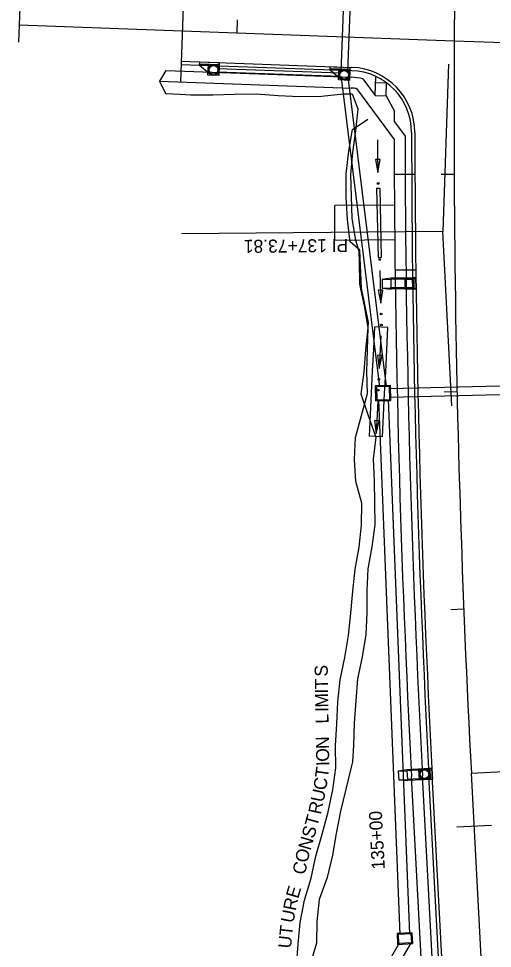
# Model space of a CAD drawing. Extents: x 979959 to 994833, y 1835619 to 1845316.
# Drawn here: x 992272.6 to 992490.3, y 1842198 to 1842625.6 of the extents above; entities that cross this region are included whole.
import ezdxf

# ---------------------------------------------------------------- set-up
doc = ezdxf.new("R2010")
doc.units = 0
for name, color, linetype in [('Future 5 Lane Construction Limits', 7, 'Continuous'), ('R_Drainage', 7, 'Continuous'), ('R_Horz Alg', 7, 'Continuous'), ('R_Horz Alg Annot', 7, 'Continuous'), ('R_Horz Alg Stationing', 7, 'Continuous'), ('R_Proposed Const Limits', 7, 'Continuous'), ('R_Proposed Road', 7, 'Continuous'), ('R_Special Ditch', 7, 'Continuous')]:
    doc.layers.add(name, color=color, linetype=linetype)

msp = doc.modelspace()

# ---------------------------------------------------------------- linework, layer by layer
at = {"layer": 'Future 5 Lane Construction Limits'}
for points in [[(992424.99, 1842522.95), (992423.66, 1842533.28), (992423.12, 1842543.66), (992423.06, 1842554.19), (992424.38, 1842564.68), (992425.98, 1842574.54), (992433.05, 1842579.38)], [(992429.11, 1842382.52), (992430.18, 1842392.64), (992430.37, 1842402.73), (992427.61, 1842412.74), (992427, 1842422.81), (992427.41, 1842432.9), (992430.07, 1842443.05), (992432.92, 1842453.19), (992432.65, 1842463.26), (992432.83, 1842473.34), (992433.22, 1842483.42), (992433.3, 1842485.84), (992430.21, 1842501.66), (992429.45, 1842519.17), (992424.99, 1842522.95)], [(992418.2, 1842291.13), (992418.74, 1842301.27), (992419.28, 1842311.41), (992420.36, 1842321.58), (992422.48, 1842331.78), (992422.96, 1842334.52), (992424.1, 1842341.95), (992425.17, 1842352.1), (992426.21, 1842362.23), (992427.21, 1842372.36), (992429.11, 1842382.52)], [(992400.25, 1842189.87), (992400.98, 1842199.92), (992402.01, 1842209.99), (992404.02, 1842220.11), (992406.97, 1842230.28), (992409.13, 1842240.41), (992412.07, 1842250.58), (992414.81, 1842260.74), (992416.98, 1842270.87), (992418.37, 1842281.01), (992418.2, 1842291.13)]]:
    msp.add_lwpolyline(points, dxfattribs=at)
at = {"layer": 'R_Drainage'}
for p, q in [((992421.89, 1842633.32), (992420.71, 1842601.17)), ((992424.89, 1842633.21), (992423.7, 1842601.06)), ((992355.77, 1842604.23), (992360.56, 1842600.1)), ((992364.79, 1842604.4), (992355.79, 1842604.73)), ((992364.6, 1842599.4), (992359.61, 1842599.58)), ((992364.02, 1842601.17), (992420.28, 1842599.11)), ((992364.08, 1842602.67), (992420.33, 1842600.61)), ((992415.73, 1842602.03), (992420.52, 1842597.9)), ((992424.75, 1842602.2), (992415.75, 1842602.53)), ((992424.56, 1842597.2), (992419.57, 1842597.39)), ((992420.83, 1842598.3), (992438.49, 1842456.32)), ((992423.81, 1842598.67), (992441.5, 1842456.38)), ((992437.08, 1842547.67), (992438.58, 1842547.7)), ((992437.08, 1842547.67), (992437.73, 1842515.68)), ((992438.58, 1842547.7), (992439.23, 1842515.71)), ((992437.73, 1842515.68), (992439.23, 1842515.71)), ((992443.65, 1842506.24), (992439.65, 1842505.7)), ((992439.65, 1842505.7), (992443.65, 1842505.74)), ((992439.65, 1842505.7), (992439.69, 1842501.7)), ((992454.15, 1842506.34), (992443.65, 1842506.24)), ((992453.65, 1842505.84), (992443.65, 1842505.74)), ((992443.65, 1842505.74), (992443.69, 1842501.74)), ((992453.65, 1842505.84), (992453.69, 1842501.84)), ((992454.15, 1842506.34), (992454.2, 1842501.34)), ((992439.69, 1842501.7), (992443.69, 1842501.74)), ((992439.69, 1842501.7), (992443.7, 1842501.24)), ((992453.69, 1842501.84), (992443.69, 1842501.74)), ((992454.2, 1842501.34), (992443.7, 1842501.24)), ((992453.7, 1842501.34), (992455.2, 1842501.35)), ((992442.3, 1842483.57), (992436.32, 1842483.89)), ((992505.5, 1842456.8), (992443.02, 1842455.42)), ((992437.88, 1842450.3), (992447.74, 1842204.4)), ((992442.38, 1842450.4), (992452.24, 1842204.64)), ((992505.59, 1842452.8), (992443.11, 1842451.42)), ((992439.79, 1842433.22), (992433.8, 1842433.51)), ((992451, 1842280.19), (992447.03, 1842279.48)), ((992447.03, 1842279.48), (992451.03, 1842279.69)), ((992447.03, 1842279.48), (992447.24, 1842275.48)), ((992461.48, 1842280.75), (992451, 1842280.19)), ((992461.01, 1842280.22), (992451.03, 1842279.69)), ((992451.03, 1842279.69), (992451.24, 1842275.7)), ((992456.76, 1842275.49), (992456.49, 1842280.48)), ((992461.01, 1842280.22), (992461.22, 1842276.23)), ((992461.48, 1842280.75), (992461.75, 1842275.75)), ((992447.24, 1842275.48), (992451.24, 1842275.7)), ((992447.24, 1842275.48), (992451.27, 1842275.2)), ((992461.22, 1842276.23), (992451.24, 1842275.7)), ((992461.75, 1842275.75), (992451.27, 1842275.2)), ((992461.25, 1842275.73), (992462.75, 1842275.81)), ((992447.51, 1842200.38), (992384.95, 1842093.69)), ((992452.89, 1842200.67), (992388.83, 1842091.42))]:
    msp.add_line(p, q, dxfattribs=at)
for points in [[(992364.77, 1842603.9), (992355.77, 1842604.23), (992355.83, 1842605.73), (992364.82, 1842605.4)], [(992364.6, 1842599.4), (992359.61, 1842599.58), (992359.79, 1842604.58), (992364.79, 1842604.4)], [(992424.73, 1842601.7), (992415.73, 1842602.03), (992415.79, 1842603.53), (992424.78, 1842603.2)], [(992424.56, 1842597.2), (992419.57, 1842597.39), (992419.75, 1842602.38), (992424.75, 1842602.2)], [(992450.19, 1842501.31), (992450.15, 1842506.31), (992454.15, 1842506.34), (992454.19, 1842501.34)], [(992450.15, 1842506.31), (992450.19, 1842501.31), (992454.19, 1842501.34), (992454.15, 1842506.34)], [(992450.69, 1842501.81), (992450.65, 1842505.81), (992453.65, 1842505.84), (992453.69, 1842501.84)], [(992450.65, 1842505.81), (992450.69, 1842501.81), (992453.69, 1842501.84), (992453.65, 1842505.84)], [(992453.69, 1842501.34), (992453.65, 1842506.34), (992455.15, 1842506.35), (992455.19, 1842501.35)], [(992436.64, 1842449.77), (992443.64, 1842449.93), (992443.48, 1842456.93), (992436.49, 1842456.77)], [(992437.13, 1842450.29), (992443.13, 1842450.42), (992443, 1842456.42), (992437, 1842456.28)], [(992456.76, 1842275.49), (992456.49, 1842280.48), (992461.48, 1842280.74), (992461.75, 1842275.75)], [(992461.25, 1842275.72), (992460.99, 1842280.72), (992462.48, 1842280.8), (992462.75, 1842275.8)], [(992446.73, 1842199.84), (992453.72, 1842200.21), (992453.46, 1842205.2), (992446.47, 1842204.83)], [(992447.2, 1842200.36), (992453.2, 1842200.68), (992452.98, 1842204.68), (992446.99, 1842204.36)]]:
    msp.add_lwpolyline(points, close=True, dxfattribs=at)
for points in [[(992455.2, 1842501.35), (992455.15, 1842506.35), (992453.65, 1842506.34), (992453.7, 1842501.34)], [(992433.8, 1842433.51), (992434.75, 1842453.45), (992435.25, 1842463.53), (992435.77, 1842473.61), (992436.32, 1842483.89)], [(992439.79, 1842433.22), (992440.75, 1842453.15), (992441.25, 1842463.23), (992441.76, 1842473.29), (992442.31, 1842483.48), (992442.3, 1842483.57)], [(992462.75, 1842275.81), (992462.48, 1842280.8), (992460.99, 1842280.72), (992461.25, 1842275.73)]]:
    msp.add_lwpolyline(points, dxfattribs=at)
for centre, radius in [((992362.2, 1842601.99), 2.5), ((992362.2, 1842601.99), 2.5), ((992362.2, 1842601.99), 2), ((992362.2, 1842601.99), 2), ((992422.16, 1842599.79), 2.5), ((992422.16, 1842599.79), 2.5), ((992422.16, 1842599.79), 2), ((992422.16, 1842599.79), 2), ((992459.12, 1842278.12), 2.5), ((992459.12, 1842278.12), 2.5), ((992459.12, 1842278.12), 2), ((992459.12, 1842278.12), 2)]:
    msp.add_circle(centre, radius, dxfattribs=at)
at = {"layer": 'R_Horz Alg'}
for p, q in [((992272.9, 1842622.77), (992472.76, 1842615.45)), ((992472.76, 1842615.45), (992772.56, 1842604.47)), ((992508.95, 1841742.22), (992480.63, 1842278.55))]:
    msp.add_line(p, q, dxfattribs=at)
msp.add_arc((998202.23, 1842580.69), 5729.58, 178.036106, 183.022805, dxfattribs=at)
at = {"layer": 'R_Horz Alg Annot'}
for p in [(992470.11, 1842604.66), (992471.71, 1842447.5)]:
    msp.add_line(p, (992467.47, 1842527.7), dxfattribs=at)
for points in [[(992467.47, 1842527.7), (992347.48, 1842526.59)], [(992480.63, 1842278.55), (992610.45, 1842285.41)]]:
    msp.add_lwpolyline(points, dxfattribs=at)
at = {"layer": 'R_Horz Alg Stationing'}
for points in [[(992273.19, 1842630.77), (992272.6, 1842614.78)], [(992373.05, 1842625.11), (992372.83, 1842619.11)], [(992466.72, 1842554.07), (992472.72, 1842554.09)], [(992468.06, 1842453.97), (992474.05, 1842454.1)], [(992471.14, 1842353.91), (992477.14, 1842354.15)], [(992473.92, 1842253.85), (992489.9, 1842254.69)]]:
    msp.add_lwpolyline(points, dxfattribs=at)
at = {"layer": 'R_Proposed Const Limits'}
for points in [[(992337.26, 1842596.9), (992340.16, 1842591.23), (992346.77, 1842590.8), (992351.77, 1842590.62), (992361.78, 1842590.61), (992371.79, 1842590.86), (992381.81, 1842591.02), (992391.79, 1842590.3), (992401.77, 1842589.77), (992411.79, 1842589.91), (992421.83, 1842591.08)], [(992421.83, 1842591.08), (992425.93, 1842591.06)], [(992425.93, 1842591.06), (992428.47, 1842584.12), (992427.42, 1842574.04), (992426.05, 1842563.96), (992425.02, 1842553.87), (992425.33, 1842543.79), (992425.75, 1842533.71), (992427.44, 1842523.64), (992428.99, 1842518.62), (992429.05, 1842513.58), (992429.17, 1842503.51), (992431.32, 1842493.46), (992433.05, 1842483.42), (992432.03, 1842473.32), (992431.22, 1842463.23), (992429.79, 1842453.12), (992433.17, 1842443.13), (992436.78, 1842433.14)], [(992436.78, 1842433.14), (992435.55, 1842423.04), (992435.97, 1842412.98), (992436.1, 1842402.91), (992436.27, 1842392.84), (992434.92, 1842382.72), (992433.12, 1842372.58), (992432.65, 1842362.48), (992432.66, 1842352.39), (992432.21, 1842342.29), (992430.39, 1842332.12), (992428.36, 1842321.94), (992427.48, 1842311.8), (992426.78, 1842301.66), (992426.53, 1842291.54), (992426.04, 1842283.85), (992425.46, 1842281.38), (992422.99, 1842271.18), (992420.55, 1842261.04), (992418.44, 1842250.92), (992416.75, 1842240.81), (992414.44, 1842230.68), (992410.63, 1842220.46), (992409.62, 1842210.39), (992409.43, 1842200.37), (992406.37, 1842190.19)]]:
    msp.add_lwpolyline(points, dxfattribs=at)
at = {"layer": 'R_Proposed Road'}
for p, q in [((992348.71, 1842643.51), (992346.98, 1842596.54)), ((992347.28, 1842604.54), (992425.7, 1842601.67)), ((992347.33, 1842606.04), (992425.76, 1842603.16)), ((992340.2, 1842601.8), (992337.26, 1842596.9)), ((992340.2, 1842601.8), (992425.59, 1842598.67)), ((992337.26, 1842596.9), (992425.41, 1842593.67)), ((992430.81, 1842597.93), (992436.47, 1842590.23)), ((992436.47, 1842590.23), (992436.79, 1842598.97)), ((992436.69, 1842596.22), (992441.69, 1842596.04)), ((992441.47, 1842590.04), (992441.69, 1842596.04)), ((992427.92, 1842593.42), (992445.17, 1842569.95)), ((992436.47, 1842590.23), (992441.47, 1842590.04)), ((992441.47, 1842590.04), (992445.38, 1842583.1)), ((992445.38, 1842578.1), (992445.38, 1842583.1)), ((992445.38, 1842578.1), (992450.16, 1842571.59)), ((992454.72, 1842553.94), (992445.22, 1842553.86)), ((992445.3, 1842539.86), (992417.88, 1842539.63)), ((992417.96, 1842523.63), (992417.88, 1842539.63)), ((992445.44, 1842523.86), (992417.96, 1842523.63)), ((992455.09, 1842509.94), (992445.59, 1842509.86)), ((992481.49, 1841740.77), (992453.17, 1842277.1)), ((992486.48, 1841741.04), (992458.16, 1842277.36)), ((992489.48, 1841741.19), (992461.15, 1842277.52)), ((992490.97, 1841741.27), (992462.65, 1842277.6))]:
    msp.add_line(p, q, dxfattribs=at)
for centre, radius, start, end in [((992424.66, 1842573.18), 28.5, 0.0744, 87.9024), ((992424.66, 1842573.18), 30, 0.0744, 87.9024), ((992424.66, 1842573.18), 25.5, 76.0433, 87.9024), ((992424.66, 1842573.18), 20.5, 80.8565, 87.9024), ((998202.23, 1842580.69), 5757.08, 180.10692, 183.022805), ((998202.23, 1842580.69), 5752.08, 180.090646, 183.022805), ((998202.23, 1842580.69), 5749.08, 180.074434, 183.022805), ((998202.23, 1842580.69), 5747.58, 180.074434, 183.022805)]:
    msp.add_arc(centre, radius, start, end, dxfattribs=at)
at = {"layer": 'R_Special Ditch'}
for p, q in [((992438.67, 1842560.82), (992436.55, 1842560.79)), ((992436.55, 1842560.79), (992437.71, 1842554.81)), ((992437.71, 1842554.81), (992438.67, 1842560.82)), ((992439.9, 1842500.77), (992437.78, 1842500.72)), ((992437.78, 1842500.72), (992438.99, 1842494.75)), ((992438.99, 1842494.75), (992439.9, 1842500.77)), ((992439.68, 1842470.67), (992437.57, 1842470.78)), ((992437.57, 1842470.78), (992438.32, 1842464.74)), ((992438.32, 1842464.74), (992439.68, 1842470.67)), ((992438.2, 1842440.68), (992436.09, 1842440.78)), ((992436.09, 1842440.78), (992436.86, 1842434.73)), ((992436.86, 1842434.73), (992438.2, 1842440.68))]:
    msp.add_line(p, q, dxfattribs=at)
for points in [[(992437.45, 1842569.8), (992437.55, 1842563.99), (992437.71, 1842554.81)], [(992437.97, 1842539.81), (992437.97, 1842539.77)], [(992438.62, 1842509.78), (992438.62, 1842509.74)], [(992438.62, 1842509.74), (992438.76, 1842503.64), (992438.99, 1842494.75)], [(992439.1, 1842479.72), (992438.77, 1842473.45), (992438.32, 1842464.74)], [(992439.1, 1842479.75), (992439.1, 1842479.72)], [(992437.58, 1842449.72), (992436.86, 1842434.73)], [(992437.58, 1842449.76), (992437.58, 1842449.72)]]:
    msp.add_lwpolyline(points, dxfattribs=at)
for centre in [(992437.83, 1842549.8), (992438.53, 1842514.76), (992439.17, 1842489.74), (992439.31, 1842484.73), (992438.11, 1842459.74), (992437.86, 1842454.73)]:
    msp.add_circle(centre, 0.375, dxfattribs=at)

# ---------------------------------------------------------------- texts
at = {"layer": 'Future 5 Lane Construction Limits'}
for s, rotation, p in [('S', 90.9339, (992414.68, 1842323.06)), ('T', 90.9339, (992414.78, 1842317.21)), ('I', 90.9339, (992414.81, 1842315.22)), ('M', 90.9339, (992414.91, 1842308.8)), ('I', 90.9339, (992414.94, 1842306.81)), ('L', 90.9339, (992415.03, 1842301.43)), ('N', 90.9339, (992415.22, 1842289.76)), ('O', 90.9339, (992415.32, 1842283.9)), ('I', 90.9339, (992415.35, 1842281.92)), ('T', 82.2196, (992414.67, 1842276.11)), ('C', 82.2196, (992413.9, 1842270.49)), ('U', 77.8957, (992412.62, 1842264.87)), ('R', 77.8957, (992411.44, 1842259.32)), ('T', 74.927, (992409.8, 1842253.69)), ('S', 73.8479, (992408.27, 1842248.24)), ('N', 73.8479, (992406.69, 1842242.79)), ('O', 78.0095, (992405.35, 1842237.09)), ('C', 78.0095, (992404.18, 1842231.55)), ('E', 73.8094, (992401.04, 1842220.6)), ('R', 78.7627, (992399.95, 1842215.04)), ('U', 78.7627, (992398.83, 1842209.38)), ('T', 84.1415, (992398.33, 1842203.54)), ('U', 84.1415, (992397.75, 1842197.81))]:
    msp.add_text(s, height=6, rotation=rotation, dxfattribs=at).set_placement(p)
at = {"layer": 'R_Horz Alg Annot'}
msp.add_text('PI 137+73.81', height=6, rotation=180.5295, dxfattribs=at).set_placement((992424, 1842524.29))
at = {"layer": 'R_Horz Alg Stationing'}
msp.add_text('135+00', height=6, rotation=93.0228, dxfattribs=at).set_placement((992440.9, 1842234.43))

doc.saveas('drawing.dxf')
